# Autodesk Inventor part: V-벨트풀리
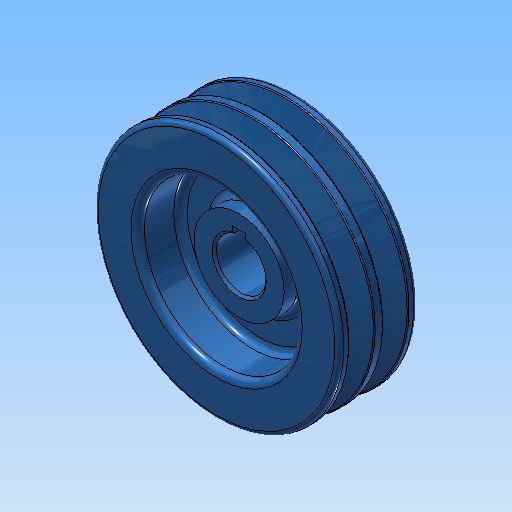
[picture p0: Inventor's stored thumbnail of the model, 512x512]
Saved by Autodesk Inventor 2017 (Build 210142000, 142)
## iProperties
Created: 2021-06
Part Number: V-벨트풀리
Material: 알루미늄 6061
Document SubType Name: Modeling
Designer: mdu
Density: 1 g/cm^3
Appearance: 청록색
CustomPartVersion: 1
Author: mdu
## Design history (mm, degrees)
sketch "주 스케치"
  geometry: L1 (0, 35)-(54.5, 35); L2 (54.5, 35)-(54.5, 15.55); L3 (54.5, 15.55)-(42, 11.488); L4 (42, 11.488)-(42, 8.512); L5 (42, 8.512)-(54.5, 4.45); L6 (54.5, 4.45)-(54.5, 0); L7 (54.5, 0)-(0, 0); L8 (50.5, 14.25)-(50.5, 5.75); L9 (42, 10)-(50.5, 10); L10 (54.5, 15.55)-(54.5, 4.45); L11 (0, -4)-(0, 24) reference; L12 (0, 0)-(0, 35)
  constraints: 22 end point, 5 perpendicular, 2 collinear, 2 midpoint, 2 point on line, 1 parallel
  dimensions: "d0" = 8.5 distance of L8.start L8.end (= da_Bw); "d1" = 36 deg angle of L3 L5 (= da_Alfa); "d2" = 4 distance between parallel lines of L2 L8 (= da_c); "d6" = 35 distance between parallel lines of L7 L1 (computed from d5, da_ng, da_Sg); "d21" = 101 diameter of L8 L11 (= da_Dw); "d25" = 12.5 distance between parallel lines of L4 L10 (= da_Hd); "d27" = 10 distance between parallel lines of L7 L9 (= da_Se)
node "평 벨트"
revolve "본체" stored, may be unused: angle "d7" = 90 deg
revolve "그루브" stored, may be unused: angle "d15" = 90 deg
fillet "외부 모깎기" dims "d8" = 0.5 (= da_r1), "d10" = 0, "da_r1" = 0.5 [user parameter; used in 1 equation term]
fillet "내부 모깎기" dims "d9" = 1 (= da_r2), "d11" = 0, "da_r2" = 1 [user parameter; used in 1 equation term]
sketch "스케치2"
  geometry: L1 (0, 0)-(0, 35); L2 (-54.5, 35)-(54.5, 35) reference; L3 (0, 35)-(35, 35); L4 (35, 35)-(35, 16); L5 (35, 16)-(20, 16); L6 (20, 16)-(20, 25); L7 (20, 25)-(0, 25); L8 (35, 0)-(35, 6); L9 (35, 6)-(20, 6); L10 (20, 6)-(20, 0); L11 (20, 0)-(35, 0); L12 (-54.5, 0)-(54.5, 0) reference
  constraints: 20 end point, 5 perpendicular, 3 parallel, 2 point on line, 2 vertical alignment, 1 collinear, 1 midpoint, 1 vertical
  dimensions: "d28" = 9 distance between parallel lines of L7 L5; "d30" = 6 distance of L9.end L10.end; "d31" = 10 distance between parallel lines of L9 L5; "d32" = 40 diameter of L10 L1; "d33" = 70 diameter of L8 L1
revolve "회전3" sketch "스케치2" stored, may be unused: angle "d34" = 90 deg
fillet "모깎기3" dims "d35" = 2, "d36" = 3
node "키홈1"
chamfer "모따기1" distance "d37" = 1; stored, may be unused: second distance "d38" = 2, angle "d39" = 45 deg
body "Solid1"
pattern_linear "그루브 패턴" dims "d18" = 15 (= da_Sg)
feature "허브 키홈"
other parameters: "da_Bw" = 8.5 [user parameter; used in 1 equation term], "da_Alfa" = 36 deg [user parameter; used in 1 equation term], "da_c" = 4 [user parameter; used in 1 equation term], "da_Dw" = 101 [user parameter; used in 1 equation term], "da_Hd" = 12.5 [user parameter; used in 1 equation term], "da_Se" = 10 [user parameter; used in 2 equation terms], "da_Sg" = 15 [user parameter; used in 2 equation terms], "d24" = 0, "d26" = 0
